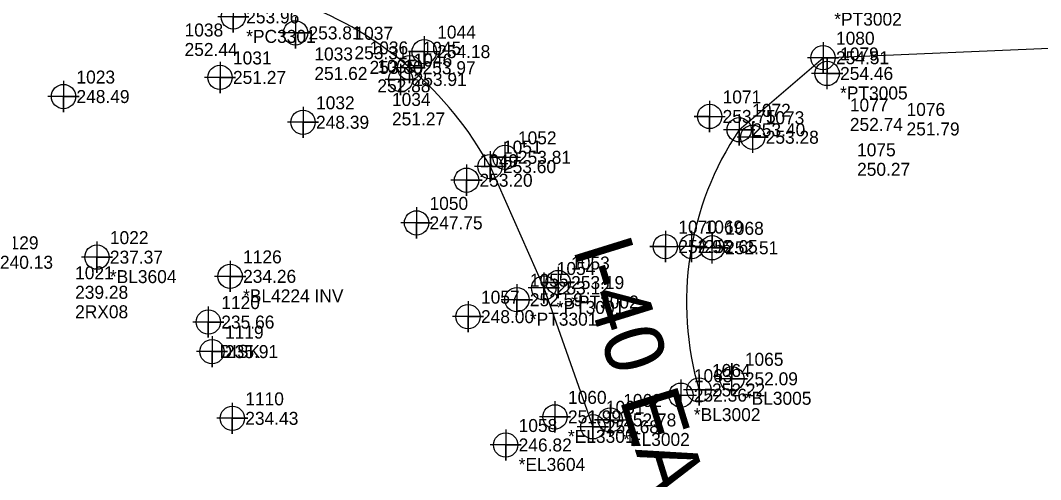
# Model space of a CAD drawing. Extents: x 2130621 to 2131998, y 642516 to 644503.
# Drawn here: x 2131142.4 to 2131338.9, y 643064.2 to 643152.6 of the extents above; entities that cross this region are included whole.
import ezdxf

# ---------------------------------------------------------------- set-up
doc = ezdxf.new("R2010")
doc.units = 0
for name, color, linetype in [('Exist Guardrail Cogo Comment', 7, 'Continuous'), ('Exist Guardrail Cogo Elevation', 7, 'Continuous'), ('Exist Guardrail Cogo Number', 7, 'Continuous'), ('Exist Guardrail Cogo Point CELL', 7, 'Continuous'), ('Exist Other Culture Anchor (Guy Wire) Cogo Elevation', 7, 'Continuous'), ('Exist Other Culture Anchor (Guy Wire) Cogo Number', 7, 'Continuous'), ('Exist Other Culture Fence Line Cogo Elevation', 7, 'Continuous'), ('Exist Other Culture Fence Line Cogo Number', 7, 'Continuous'), ('Exist Other Culture Fence Line Cogo Point CELL', 7, 'Continuous'), ('Exist Other Culture Sign Cogo Elevation', 7, 'Continuous'), ('Exist Other Culture Sign Cogo Number', 7, 'Continuous'), ('Exist Right of Way Monument Cogo Comment', 7, 'Continuous'), ('Exist Roads EOP', 7, 'Continuous'), ('Exist Roads EOP Cogo Comment', 7, 'Continuous'), ('Exist Roads EOP Cogo Elevation', 7, 'Continuous'), ('Exist Roads EOP Cogo Number', 7, 'Continuous'), ('Exist Roads EOP Cogo Point CELL', 7, 'Continuous'), ('Exist Roads EOT Cogo Comment', 7, 'Continuous'), ('Exist Roads EOT Cogo Elevation', 7, 'Continuous'), ('Exist Roads EOT Cogo Number', 7, 'Continuous'), ('Exist Roads EOT Cogo Point CELL', 7, 'Continuous'), ('Exist Roads EOT Text', 7, 'Continuous'), ('Exist Roads Soil Cogo Comment', 7, 'Continuous'), ('Exist Roads Soil Cogo Elevation', 7, 'Continuous'), ('Exist Roads Soil Cogo Number', 7, 'Continuous'), ('Exist Roads Soil Cogo Point CELL', 7, 'Continuous'), ('Exist Structure Minor Pipes RCP 24 Inch Cogo Comment', 7, 'Continuous'), ('Exist Structure Minor Pipes RCP 24 Inch Cogo Elevation', 7, 'Continuous'), ('Exist Structure Minor Pipes RCP 24 Inch Cogo Number', 7, 'Continuous'), ('Exist Structure Minor Pipes RCP 24 Inch Cogo Point CELL', 7, 'Continuous'), ('Exist Utilities Other Traffic Signal Box Cogo Elevation', 7, 'Continuous'), ('Exist Utilities Other Traffic Signal Box Cogo Number', 7, 'Continuous'), ('Exist Utilities Power Joint Use Telephone Cogo Comment', 7, 'Continuous'), ('Exist Utilities Power Joint Use Telephone Cogo Elevation', 7, 'Continuous'), ('Exist Utilities Power Joint Use Telephone Cogo Number', 7, 'Continuous'), ('Exist Utilities Power Pole Cogo Elevation', 7, 'Continuous'), ('Exist Utilities Power Pole Cogo Number', 7, 'Continuous'), ('Exist Vegetation Woods Line Cogo Comment', 7, 'Continuous'), ('Exist Vegetation Woods Line Cogo Elevation', 7, 'Continuous'), ('Exist Vegetation Woods Line Cogo Number', 7, 'Continuous'), ('Exist Vegetation Woods Line Cogo Point CELL', 7, 'Continuous')]:
    doc.layers.add(name, color=color, linetype=linetype)

msp = doc.modelspace()

# ---------------------------------------------------------------- linework, layer by layer
at = {"layer": 'Exist Guardrail Cogo Point CELL'}
for points in [[(2131183.35, 643156.25), (2131183.35, 643150.25), (2131183.35, 643153.25), (2131186.35, 643153.25), (2131180.35, 643153.25)], [(2131195.35, 643153.17), (2131195.35, 643147.17), (2131195.35, 643150.17), (2131198.35, 643150.17), (2131192.35, 643150.17)], [(2131215.6, 643144.2), (2131215.6, 643138.2), (2131215.6, 643141.2), (2131218.6, 643141.2), (2131212.6, 643141.2)], [(2131228.29, 643124.81), (2131228.29, 643118.81), (2131228.29, 643121.81), (2131231.29, 643121.81), (2131225.29, 643121.81)], [(2131237.99, 643101.81), (2131237.99, 643095.81), (2131237.99, 643098.81), (2131240.99, 643098.81), (2131234.99, 643098.81)], [(2131245.33, 643079.26), (2131245.33, 643073.26), (2131245.33, 643076.26), (2131248.33, 643076.26), (2131242.33, 643076.26)]]:
    msp.add_lwpolyline(points, dxfattribs=at)
for centre in [(2131183.35, 643153.25), (2131195.35, 643150.17), (2131215.6, 643141.2), (2131228.29, 643121.81), (2131237.99, 643098.81), (2131245.33, 643076.26)]:
    msp.add_circle(centre, 2.34, dxfattribs=at)
at = {"layer": 'Exist Other Culture Fence Line Cogo Point CELL'}
for points in [[(2131178.55, 643097.51), (2131178.55, 643091.51), (2131178.55, 643094.51), (2131181.55, 643094.51), (2131175.55, 643094.51)], [(2131179.27, 643091.82), (2131179.27, 643085.82), (2131179.27, 643088.82), (2131182.27, 643088.82), (2131176.27, 643088.82)], [(2131183.17, 643078.98), (2131183.17, 643072.98), (2131183.17, 643075.98), (2131186.17, 643075.98), (2131180.17, 643075.98)]]:
    msp.add_lwpolyline(points, dxfattribs=at)
for centre in [(2131178.55, 643094.51), (2131179.27, 643088.82), (2131183.17, 643075.98)]:
    msp.add_circle(centre, 2.34, dxfattribs=at)
at = {"layer": 'Exist Roads EOP'}
for points in [[(2131280.81, 643131.52), (2131296.96, 643145.39), (2131345.05, 643147.42), (2131395.77, 643145.79), (2131444.21, 643144.25)], [(2131232.81, 643124.43), (2131243.17, 643101.07), (2131252.63, 643074.35)]]:
    msp.add_lwpolyline(points, dxfattribs=at)
for centre, major_axis, ratio, start_param, end_param in [((2131171.86, 643090.73), (-59.45, 36.39), 0.999021, 4.196396, 4.901283), ((2131330.15, 643098.22), (24.44, -54.29), 0.999074, 3.696142, 4.575451)]:
    msp.add_ellipse(centre, major_axis=major_axis, ratio=ratio, start_param=start_param, end_param=end_param, dxfattribs=at)
at = {"layer": 'Exist Roads EOP Cogo Point CELL'}
for points in [[(2131296.96, 643148.39), (2131296.96, 643142.39), (2131296.96, 643145.39), (2131299.96, 643145.39), (2131293.96, 643145.39)], [(2131217.32, 643146.47), (2131217.32, 643140.47), (2131217.32, 643143.47), (2131220.32, 643143.47), (2131214.32, 643143.47)], [(2131280.81, 643134.52), (2131280.81, 643128.52), (2131280.81, 643131.52), (2131283.81, 643131.52), (2131277.81, 643131.52)], [(2131232.81, 643127.43), (2131232.81, 643121.43), (2131232.81, 643124.43), (2131235.81, 643124.43), (2131229.81, 643124.43)], [(2131271.65, 643112.05), (2131271.65, 643106.05), (2131271.65, 643109.05), (2131274.65, 643109.05), (2131268.65, 643109.05)], [(2131243.17, 643104.07), (2131243.17, 643098.07), (2131243.17, 643101.07), (2131246.17, 643101.07), (2131240.17, 643101.07)], [(2131273.08, 643084.44), (2131273.08, 643078.44), (2131273.08, 643081.44), (2131276.08, 643081.44), (2131270.08, 643081.44)], [(2131252.63, 643077.35), (2131252.63, 643071.35), (2131252.63, 643074.35), (2131255.63, 643074.35), (2131249.63, 643074.35)]]:
    msp.add_lwpolyline(points, dxfattribs=at)
for centre in [(2131296.96, 643145.39), (2131217.32, 643143.47), (2131280.81, 643131.52), (2131232.81, 643124.43), (2131271.65, 643109.05), (2131243.17, 643101.07), (2131273.08, 643081.44), (2131252.63, 643074.35)]:
    msp.add_circle(centre, 2.34, dxfattribs=at)
at = {"layer": 'Exist Roads EOT Cogo Point CELL'}
for points in [[(2131220.14, 643149.57), (2131220.14, 643143.57), (2131220.14, 643146.57), (2131217.14, 643146.57), (2131223.14, 643146.57)], [(2131275.12, 643137.09), (2131275.12, 643131.09), (2131275.12, 643134.09), (2131272.12, 643134.09), (2131278.12, 643134.09)], [(2131235.69, 643129.22), (2131235.69, 643123.22), (2131235.69, 643126.22), (2131232.69, 643126.22), (2131238.69, 643126.22)], [(2131266.59, 643112.04), (2131266.59, 643106.04), (2131266.59, 643109.04), (2131263.59, 643109.04), (2131269.59, 643109.04)], [(2131245.94, 643105.12), (2131245.94, 643099.12), (2131245.94, 643102.12), (2131242.94, 643102.12), (2131248.94, 643102.12)], [(2131269.58, 643083.44), (2131269.58, 643077.44), (2131269.58, 643080.44), (2131266.58, 643080.44), (2131272.58, 643080.44)], [(2131255.97, 643078.67), (2131255.97, 643072.67), (2131255.97, 643075.67), (2131252.97, 643075.67), (2131258.97, 643075.67)]]:
    msp.add_lwpolyline(points, dxfattribs=at)
for centre in [(2131220.14, 643146.57), (2131275.12, 643134.09), (2131235.69, 643126.22), (2131266.59, 643109.04), (2131245.94, 643102.12), (2131269.58, 643080.44), (2131255.97, 643075.67)]:
    msp.add_circle(centre, 2.34, dxfattribs=at)
at = {"layer": 'Exist Roads Soil Cogo Point CELL'}
for points in [[(2131297.75, 643139.36), (2131297.75, 643145.36), (2131297.75, 643142.36), (2131300.75, 643142.36), (2131294.75, 643142.36)], [(2131283.42, 643127.09), (2131283.42, 643133.09), (2131283.42, 643130.09), (2131286.42, 643130.09), (2131280.42, 643130.09)], [(2131275.61, 643105.81), (2131275.61, 643111.81), (2131275.61, 643108.81), (2131278.61, 643108.81), (2131272.61, 643108.81)], [(2131279.4, 643080.59), (2131279.4, 643086.59), (2131279.4, 643083.59), (2131282.4, 643083.59), (2131276.4, 643083.59)]]:
    msp.add_lwpolyline(points, dxfattribs=at)
for centre in [(2131297.75, 643142.36), (2131283.42, 643130.09), (2131275.61, 643108.81), (2131279.4, 643083.59)]:
    msp.add_circle(centre, 2.34, dxfattribs=at)
at = {"layer": 'Exist Structure Minor Pipes RCP 24 Inch Cogo Point CELL'}
msp.add_lwpolyline([(2131182.75, 643106.31), (2131182.75, 643100.31), (2131182.75, 643103.31), (2131185.75, 643103.31), (2131179.75, 643103.31)], dxfattribs=at)
msp.add_circle((2131182.75, 643103.31), 2.34, dxfattribs=at)
at = {"layer": 'Exist Vegetation Woods Line Cogo Point CELL'}
for points in [[(2131180.8, 643144.6), (2131180.8, 643138.6), (2131180.8, 643141.6), (2131183.8, 643141.6), (2131177.8, 643141.6)], [(2131150.65, 643140.92), (2131150.65, 643134.92), (2131150.65, 643137.92), (2131153.65, 643137.92), (2131147.65, 643137.92)], [(2131196.8, 643135.97), (2131196.8, 643129.97), (2131196.8, 643132.97), (2131199.8, 643132.97), (2131193.8, 643132.97)], [(2131218.66, 643116.6), (2131218.66, 643110.6), (2131218.66, 643113.6), (2131221.66, 643113.6), (2131215.66, 643113.6)], [(2131157.09, 643110.01), (2131157.09, 643104.01), (2131157.09, 643107.01), (2131160.09, 643107.01), (2131154.09, 643107.01)], [(2131228.58, 643098.55), (2131228.58, 643092.55), (2131228.58, 643095.55), (2131231.58, 643095.55), (2131225.58, 643095.55)], [(2131235.83, 643073.85), (2131235.83, 643067.85), (2131235.83, 643070.85), (2131238.83, 643070.85), (2131232.83, 643070.85)]]:
    msp.add_lwpolyline(points, dxfattribs=at)
for centre in [(2131180.8, 643141.6), (2131150.65, 643137.92), (2131196.8, 643132.97), (2131218.66, 643113.6), (2131157.09, 643107.01), (2131228.58, 643095.55), (2131235.83, 643070.85)]:
    msp.add_circle(centre, 2.34, dxfattribs=at)

# ---------------------------------------------------------------- texts
at = {"layer": 'Exist Guardrail Cogo Comment'}
for s, p in [('*PC3301', (2131185.85, 643148.25)), ('*PT3301', (2131240.49, 643093.81)), ('*EL3301', (2131247.83, 643071.26))]:
    msp.add_text(s, height=2.5, dxfattribs=at).set_placement(p)
at = {"layer": 'Exist Guardrail Cogo Elevation'}
for s, p in [('253.96', (2131185.85, 643152)), ('253.81', (2131197.85, 643148.92)), ('253.91', (2131218.1, 643139.95)), ('253.20', (2131230.79, 643120.56)), ('252.59', (2131240.49, 643097.56)), ('251.99', (2131247.83, 643075.01))]:
    msp.add_text(s, height=2.5, dxfattribs=at).set_placement(p)
at = {"layer": 'Exist Guardrail Cogo Number'}
for s, p in [('1046', (2131218.1, 643143.7)), ('1049', (2131230.79, 643124.31)), ('1055', (2131240.49, 643101.31)), ('1060', (2131247.83, 643078.76))]:
    msp.add_text(s, height=2.5, dxfattribs=at).set_placement(p)
at = {"layer": 'Exist Other Culture Anchor (Guy Wire) Cogo Elevation'}
for s, p in [('251.62', (2131198.98, 643141.11)), ('251.27', (2131213.93, 643132.36)), ('251.79', (2131313.05, 643130.43)), ('250.27', (2131303.52, 643122.66))]:
    msp.add_text(s, height=2.5, dxfattribs=at).set_placement(p)
at = {"layer": 'Exist Other Culture Anchor (Guy Wire) Cogo Number'}
for s, p in [('1033', (2131198.98, 643144.86)), ('1034', (2131213.93, 643136.11)), ('1076', (2131313.05, 643134.18)), ('1075', (2131303.52, 643126.41))]:
    msp.add_text(s, height=2.5, dxfattribs=at).set_placement(p)
at = {"layer": 'Exist Other Culture Fence Line Cogo Elevation'}
for s, p in [('240.13', (2131138.41, 643104.77)), ('235.66', (2131181.05, 643093.26)), ('235.91', (2131181.77, 643087.57)), ('234.43', (2131185.67, 643074.73))]:
    msp.add_text(s, height=2.5, dxfattribs=at).set_placement(p)
at = {"layer": 'Exist Other Culture Fence Line Cogo Number'}
for s, p in [('1129', (2131138.41, 643108.52)), ('1120', (2131181.05, 643097.01)), ('1119', (2131181.77, 643091.32)), ('1110', (2131185.67, 643078.48))]:
    msp.add_text(s, height=2.5, dxfattribs=at).set_placement(p)
at = {"layer": 'Exist Other Culture Sign Cogo Elevation'}
for s, p in [('252.44', (2131173.98, 643145.73)), ('253.31', (2131206.7, 643145.1))]:
    msp.add_text(s, height=2.5, dxfattribs=at).set_placement(p)
at = {"layer": 'Exist Other Culture Sign Cogo Number'}
for s, p in [('1038', (2131173.98, 643149.48)), ('1037', (2131206.7, 643148.85))]:
    msp.add_text(s, height=2.5, dxfattribs=at).set_placement(p)
at = {"layer": 'Exist Right of Way Monument Cogo Comment'}
msp.add_text('DISK', height=2.5, dxfattribs=at).set_placement((2131180.73, 643087.61))
at = {"layer": 'Exist Roads EOP Cogo Comment'}
msp.add_text('*PT3001', height=2.5, dxfattribs=at).set_placement((2131245.67, 643096.07))
at = {"layer": 'Exist Roads EOP Cogo Elevation'}
for s, p in [('254.51', (2131299.46, 643144.14)), ('253.97', (2131219.82, 643142.22)), ('253.40', (2131283.31, 643130.27)), ('253.60', (2131235.31, 643123.18)), ('252.65', (2131274.15, 643107.8)), ('253.12', (2131245.67, 643099.82)), ('252.22', (2131275.58, 643080.19)), ('252.68', (2131255.13, 643073.1))]:
    msp.add_text(s, height=2.5, dxfattribs=at).set_placement(p)
at = {"layer": 'Exist Roads EOP Cogo Number'}
for s, p in [('1045', (2131219.82, 643145.97)), ('1080', (2131299.46, 643147.89)), ('1072', (2131283.31, 643134.02)), ('1051', (2131235.31, 643126.93)), ('1069', (2131274.15, 643111.55)), ('1054', (2131245.67, 643103.57)), ('1064', (2131275.58, 643083.94)), ('1061', (2131255.13, 643076.85))]:
    msp.add_text(s, height=2.5, dxfattribs=at).set_placement(p)
at = {"layer": 'Exist Roads EOT Cogo Comment'}
for s, p in [('*PT3002', (2131299.13, 643151.57)), ('*PT3002', (2131248.44, 643097.12)), ('*BL3002', (2131272.08, 643075.44)), ('*EL3002', (2131258.47, 643070.67))]:
    msp.add_text(s, height=2.5, dxfattribs=at).set_placement(p)
at = {"layer": 'Exist Roads EOT Cogo Elevation'}
for s, p in [('254.18', (2131222.64, 643145.32)), ('253.75', (2131277.62, 643132.84)), ('253.81', (2131238.19, 643124.97)), ('252.96', (2131269.09, 643107.79)), ('253.19', (2131248.44, 643100.87)), ('252.36', (2131272.08, 643079.19)), ('252.78', (2131258.47, 643074.42))]:
    msp.add_text(s, height=2.5, dxfattribs=at).set_placement(p)
at = {"layer": 'Exist Roads EOT Cogo Number'}
for s, p in [('1044', (2131222.64, 643149.07)), ('1071', (2131277.62, 643136.59)), ('1052', (2131238.19, 643128.72)), ('1070', (2131269.09, 643111.54)), ('1053', (2131248.44, 643104.62)), ('1063', (2131272.08, 643082.94)), ('1062', (2131258.47, 643078.17))]:
    msp.add_text(s, height=2.5, dxfattribs=at).set_placement(p)
at = {"layer": 'Exist Roads EOT Text'}
msp.add_text('I-40 EAST BOUND ON RAMP', height=11.3735, rotation=287.2196, dxfattribs=at).set_placement((2131248.69, 643108.72))
at = {"layer": 'Exist Roads Soil Cogo Comment'}
for s, p in [('*PT3005', (2131300.25, 643137.36)), ('*BL3005', (2131281.9, 643078.59))]:
    msp.add_text(s, height=2.5, dxfattribs=at).set_placement(p)
at = {"layer": 'Exist Roads Soil Cogo Elevation'}
for s, p in [('254.46', (2131300.25, 643141.11)), ('253.28', (2131285.92, 643128.84)), ('252.51', (2131278.11, 643107.56)), ('252.09', (2131281.9, 643082.34))]:
    msp.add_text(s, height=2.5, dxfattribs=at).set_placement(p)
at = {"layer": 'Exist Roads Soil Cogo Number'}
for s, p in [('1079', (2131300.25, 643144.86)), ('1073', (2131285.92, 643132.59)), ('1068', (2131278.11, 643111.31)), ('1065', (2131281.9, 643086.09))]:
    msp.add_text(s, height=2.5, dxfattribs=at).set_placement(p)
at = {"layer": 'Exist Structure Minor Pipes RCP 24 Inch Cogo Comment'}
msp.add_text('*BL4224 INV', height=2.5, dxfattribs=at).set_placement((2131185.25, 643098.31))
at = {"layer": 'Exist Structure Minor Pipes RCP 24 Inch Cogo Elevation'}
msp.add_text('234.26', height=2.5, dxfattribs=at).set_placement((2131185.25, 643102.06))
at = {"layer": 'Exist Structure Minor Pipes RCP 24 Inch Cogo Number'}
msp.add_text('1126', height=2.5, dxfattribs=at).set_placement((2131185.25, 643105.81))
at = {"layer": 'Exist Utilities Other Traffic Signal Box Cogo Elevation'}
msp.add_text('253.30', height=2.5, dxfattribs=at).set_placement((2131209.61, 643142.29))
at = {"layer": 'Exist Utilities Other Traffic Signal Box Cogo Number'}
msp.add_text('1036', height=2.5, dxfattribs=at).set_placement((2131209.61, 643146.04))
at = {"layer": 'Exist Utilities Power Joint Use Telephone Cogo Comment'}
msp.add_text('2RX08', height=2.5, dxfattribs=at).set_placement((2131152.89, 643095.24))
at = {"layer": 'Exist Utilities Power Joint Use Telephone Cogo Elevation'}
msp.add_text('239.28', height=2.5, dxfattribs=at).set_placement((2131152.89, 643098.99))
at = {"layer": 'Exist Utilities Power Joint Use Telephone Cogo Number'}
msp.add_text('1021', height=2.5, dxfattribs=at).set_placement((2131152.89, 643102.74))
at = {"layer": 'Exist Utilities Power Pole Cogo Elevation'}
for s, p in [('252.88', (2131211.11, 643138.74)), ('252.74', (2131302.13, 643131.3))]:
    msp.add_text(s, height=2.5, dxfattribs=at).set_placement(p)
at = {"layer": 'Exist Utilities Power Pole Cogo Number'}
for s, p in [('1035', (2131211.11, 643142.49)), ('1077', (2131302.13, 643135.05))]:
    msp.add_text(s, height=2.5, dxfattribs=at).set_placement(p)
at = {"layer": 'Exist Vegetation Woods Line Cogo Comment'}
for s, p in [('*BL3604', (2131159.59, 643102.01)), ('*EL3604', (2131238.33, 643065.85))]:
    msp.add_text(s, height=2.5, dxfattribs=at).set_placement(p)
at = {"layer": 'Exist Vegetation Woods Line Cogo Elevation'}
for s, p in [('251.27', (2131183.3, 643140.35)), ('248.49', (2131153.15, 643136.67)), ('248.39', (2131199.3, 643131.72)), ('247.75', (2131221.16, 643112.35)), ('237.37', (2131159.59, 643105.76)), ('248.00', (2131231.08, 643094.3)), ('246.82', (2131238.33, 643069.6))]:
    msp.add_text(s, height=2.5, dxfattribs=at).set_placement(p)
at = {"layer": 'Exist Vegetation Woods Line Cogo Number'}
for s, p in [('1031', (2131183.3, 643144.1)), ('1023', (2131153.15, 643140.42)), ('1032', (2131199.3, 643135.47)), ('1050', (2131221.16, 643116.1)), ('1022', (2131159.59, 643109.51)), ('1057', (2131231.08, 643098.05)), ('1058', (2131238.33, 643073.35))]:
    msp.add_text(s, height=2.5, dxfattribs=at).set_placement(p)

doc.saveas('drawing.dxf')
